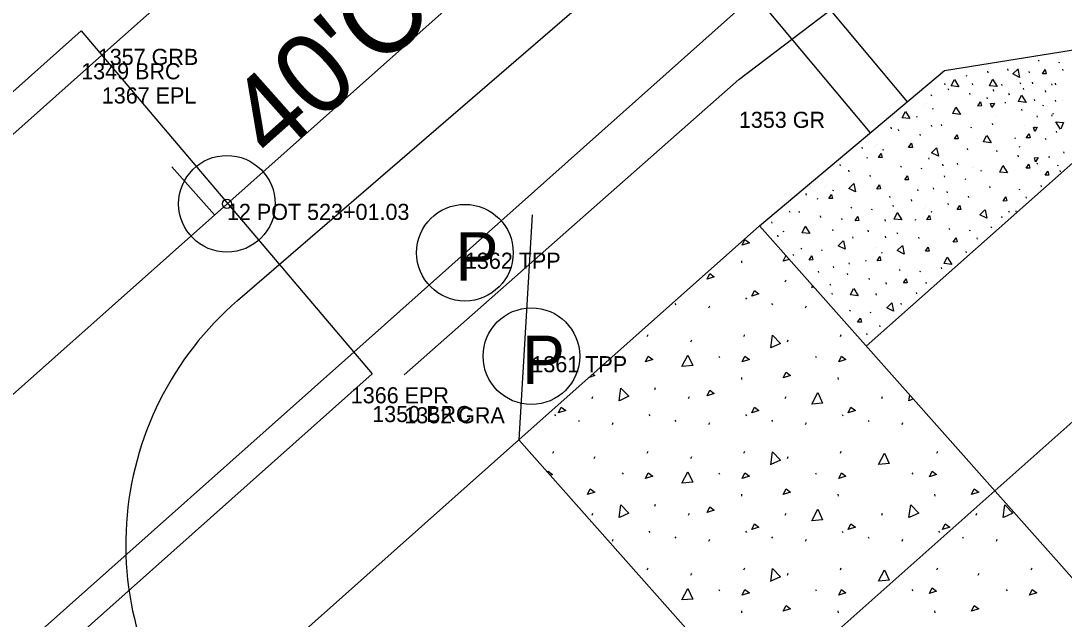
# Model space of a CAD drawing. Extents: x 50001 to 56005, y 49075 to 53926.
# Drawn here: x 53878.2 to 53943.1, y 51854.2 to 51891.3 of the extents above; entities that cross this region are included whole.
import ezdxf

# ---------------------------------------------------------------- set-up
doc = ezdxf.new("R2010")
doc.units = 0
for name, color, linetype in [('Level 1', 7, 'Continuous'), ('Level 15', 7, 'Continuous'), ('Level 18', 7, 'Continuous'), ('Level 19', 7, 'Continuous'), ('Level 20', 7, 'Continuous'), ('Level 3', 7, 'Continuous'), ('Level 5', 7, 'Continuous'), ('Level 51', 7, 'Continuous'), ('Level 53', 7, 'Continuous'), ('Level 55', 7, 'Continuous'), ('Level 57', 7, 'Continuous'), ('Level 59', 7, 'Continuous'), ('Level 7', 7, 'Continuous'), ('Level 8', 7, 'Continuous'), ('Level 9', 7, 'Continuous')]:
    doc.layers.add(name, color=color, linetype=linetype)

# ---------------------------------------------------------------- blocks, each defined once
blk = doc.blocks.new('PC')
at = {"layer": 'Level 1'}
for radius in [3, 0.282]:
    blk.add_circle((0, 0), radius, dxfattribs=at)
blk = doc.blocks.new('TPP')
at = {"layer": 'Level 9'}
blk.add_circle((0, 0), 3, dxfattribs=at)
blk.add_text('P', height=3, dxfattribs=at).set_placement((-0.589, -1.729))

msp = doc.modelspace()

# ---------------------------------------------------------------- linework, layer by layer
at = {"layer": 'Level 1'}
for p, q in [((52544.807, 50683.302), (55534.583, 53340.862)), ((52714.147, 50773.616), (54181.768, 52078.16)), ((53890.278, 51879.268), (53887.621, 51882.257))]:
    msp.add_line(p, q, dxfattribs=at)
at = {"layer": 'Level 15'}
for p, q in [((53910.003, 51879.272), (53909.18, 51865.296)), ((53909.18, 51865.296), (53924.129, 51878.584)), ((53924.129, 51878.584), (53953.361, 51845.698)), ((53923.006, 51876.413), (53923.02, 51876.288)), ((53925.731, 51875.108), (53925.786, 51875.233)), ((53923.263, 51874.123), (53923.318, 51874.04)), ((53918.882, 51873.77), (53918.937, 51873.687)), ((53920.993, 51873.499), (53921.049, 51873.623)), ((53924.882, 51873.77), (53924.937, 51873.687)), ((53926.993, 51873.499), (53927.049, 51873.623)), ((53917.158, 51871.709), (53917.213, 51871.834)), ((53919.869, 51871.39), (53919.925, 51871.514)), ((53923.158, 51871.709), (53923.213, 51871.834)), ((53925.869, 51871.39), (53925.925, 51871.514)), ((53929.158, 51871.709), (53929.213, 51871.834)), ((53915.604, 51870.502), (53915.659, 51870.418)), ((53921.604, 51870.502), (53921.659, 51870.418)), ((53927.604, 51870.502), (53927.659, 51870.418)), ((53923.006, 51869.171), (53923.02, 51869.046)), ((53929.006, 51869.171), (53929.02, 51869.046)), ((53917.622, 51868.434), (53917.677, 51868.559)), ((53913.731, 51867.865), (53913.786, 51867.99)), ((53919.731, 51867.865), (53919.786, 51867.99)), ((53925.731, 51867.865), (53925.786, 51867.99)), ((53931.731, 51867.865), (53931.786, 51867.99)), ((53911.406, 51866.881), (53911.461, 51866.797)), ((53917.263, 51866.881), (53917.318, 51866.797)), ((53923.263, 51866.881), (53923.318, 51866.797)), ((53929.263, 51866.881), (53929.318, 51866.797)), ((53912.882, 51866.527), (53912.937, 51866.444)), ((53914.993, 51866.256), (53915.049, 51866.381)), ((53918.882, 51866.527), (53918.937, 51866.444)), ((53920.993, 51866.256), (53921.049, 51866.381)), ((53924.882, 51866.527), (53924.937, 51866.444)), ((53926.993, 51866.256), (53927.049, 51866.381)), ((53930.882, 51866.527), (53930.937, 51866.444)), ((53932.993, 51866.256), (53933.049, 51866.381)), ((53460.734, 51466.679), (53909.18, 51865.296)), ((53938.412, 51832.41), (53909.18, 51865.296)), ((53911.301, 51864.466), (53911.356, 51864.591)), ((53913.869, 51864.147), (53913.925, 51864.272)), ((53917.158, 51864.466), (53917.213, 51864.591)), ((53919.869, 51864.147), (53919.925, 51864.272)), ((53923.158, 51864.466), (53923.213, 51864.591)), ((53925.869, 51864.147), (53925.925, 51864.272)), ((53929.158, 51864.466), (53929.213, 51864.591)), ((53935.158, 51864.466), (53935.213, 51864.591)), ((53915.604, 51863.259), (53915.659, 51863.176)), ((53921.604, 51863.259), (53921.659, 51863.176)), ((53927.604, 51863.259), (53927.659, 51863.176)), ((53933.604, 51863.259), (53933.659, 51863.176)), ((53923.006, 51861.928), (53923.02, 51861.803)), ((53929.006, 51861.928), (53929.02, 51861.803)), ((53935.006, 51861.928), (53935.02, 51861.803)), ((53917.622, 51861.192), (53917.677, 51861.317)), ((53913.731, 51860.623), (53913.786, 51860.748)), ((53919.731, 51860.623), (53919.786, 51860.748)), ((53925.731, 51860.623), (53925.786, 51860.748)), ((53931.731, 51860.623), (53931.786, 51860.748)), ((53937.588, 51860.623), (53937.643, 51860.748)), ((53914.993, 51859.013), (53915.049, 51859.138)), ((53917.263, 51859.638), (53917.318, 51859.555)), ((53918.882, 51859.285), (53918.937, 51859.202)), ((53920.993, 51859.013), (53921.049, 51859.138)), ((53923.263, 51859.638), (53923.318, 51859.555)), ((53924.882, 51859.285), (53924.937, 51859.202)), ((53926.993, 51859.013), (53927.049, 51859.138)), ((53929.263, 51859.638), (53929.318, 51859.555)), ((53930.882, 51859.285), (53930.937, 51859.202)), ((53932.993, 51859.013), (53933.049, 51859.138)), ((53935.263, 51859.638), (53935.318, 51859.555)), ((53936.739, 51859.285), (53936.795, 51859.202)), ((53938.85, 51859.013), (53938.906, 51859.138)), ((53917.158, 51857.223), (53917.213, 51857.348)), ((53923.158, 51857.223), (53923.213, 51857.348)), ((53929.158, 51857.223), (53929.213, 51857.348)), ((53935.158, 51857.223), (53935.213, 51857.348)), ((53941.015, 51857.223), (53941.07, 51857.348)), ((53919.869, 51856.904), (53919.925, 51857.029)), ((53925.869, 51856.904), (53925.925, 51857.029)), ((53937.726, 51856.904), (53937.782, 51857.029)), ((53921.604, 51856.016), (53921.659, 51855.933)), ((53927.604, 51856.016), (53927.659, 51855.933)), ((53933.604, 51856.016), (53933.659, 51855.933)), ((53939.461, 51856.016), (53939.516, 51855.933)), ((53923.006, 51854.685), (53923.02, 51854.56)), ((53929.006, 51854.685), (53929.02, 51854.56)), ((53935.006, 51854.685), (53935.02, 51854.56))]:
    msp.add_line(p, q, dxfattribs=at)
for points in [[(53923.061, 51877.384), (53923.227, 51877.73), (53923.505, 51877.522), (53923.061, 51877.384)], [(53925.614, 51876.392), (53925.776, 51876.73)], [(53925.976, 51876.505), (53925.614, 51876.392)], [(53920.874, 51875.278), (53921.04, 51875.625), (53921.318, 51875.417), (53920.874, 51875.278)], [(53923.649, 51874.22), (53923.816, 51874.567), (53924.093, 51874.359), (53923.649, 51874.22)], [(53927.379, 51874.766), (53927.432, 51874.867)], [(53927.513, 51874.776), (53927.393, 51874.766)], [(53924.829, 51871.002), (53924.939, 51871.795), (53925.436, 51871.282), (53924.842, 51871.007)], [(53917.061, 51870.141), (53917.227, 51870.488), (53917.505, 51870.28), (53917.061, 51870.141)], [(53919.318, 51869.851), (53919.692, 51870.559), (53919.984, 51869.907), (53919.331, 51869.851)], [(53923.061, 51870.141), (53923.227, 51870.488), (53923.505, 51870.28), (53923.061, 51870.141)], [(53929.061, 51870.141), (53929.227, 51870.488), (53929.505, 51870.28), (53929.061, 51870.141)], [(53925.614, 51869.149), (53925.781, 51869.496), (53926.058, 51869.288), (53925.614, 51869.149)], [(53913.776, 51869.381), (53913.9, 51869.288), (53913.547, 51869.178)], [(53915.419, 51867.722), (53915.529, 51868.515), (53916.026, 51868.002), (53915.432, 51867.727)], [(53920.874, 51868.035), (53921.04, 51868.382), (53921.318, 51868.174), (53920.874, 51868.035)], [(53927.379, 51867.523), (53927.754, 51868.231), (53928.045, 51867.579), (53927.393, 51867.523)], [(53933.419, 51867.722), (53933.468, 51868.077)], [(53933.678, 51867.841), (53933.432, 51867.727)], [(53911.649, 51866.977), (53911.816, 51867.324), (53912.093, 51867.116), (53911.649, 51866.977)], [(53923.649, 51866.977), (53923.816, 51867.324), (53924.093, 51867.116), (53923.649, 51866.977)], [(53929.649, 51866.977), (53929.816, 51867.324), (53930.093, 51867.116), (53929.649, 51866.977)], [(53924.829, 51863.759), (53924.939, 51864.552), (53925.436, 51864.039), (53924.842, 51863.764)], [(53931.529, 51863.772), (53931.904, 51864.48), (53932.195, 51863.828), (53931.543, 51863.772)], [(53910.968, 51863.285), (53911, 51863.351), (53911.277, 51863.143), (53911.134, 51863.098)], [(53917.061, 51862.898), (53917.227, 51863.245), (53917.505, 51863.037), (53917.061, 51862.898)], [(53919.318, 51862.609), (53919.692, 51863.316), (53919.984, 51862.664), (53919.331, 51862.609)], [(53923.061, 51862.898), (53923.227, 51863.245), (53923.505, 51863.037), (53923.061, 51862.898)], [(53929.061, 51862.898), (53929.227, 51863.245), (53929.505, 51863.037), (53929.061, 51862.898)], [(53934.691, 51863.004), (53934.857, 51863.351), (53935.135, 51863.143), (53934.691, 51863.004)], [(53913.456, 51861.906), (53913.622, 51862.253), (53913.9, 51862.045), (53913.456, 51861.906)], [(53925.614, 51861.907), (53925.781, 51862.253), (53926.058, 51862.045), (53925.614, 51861.907)], [(53937.313, 51861.906), (53937.479, 51862.253), (53937.757, 51862.045), (53937.313, 51861.906)], [(53915.419, 51860.479), (53915.529, 51861.272), (53916.026, 51860.759), (53915.432, 51860.484)], [(53920.874, 51860.793), (53921.04, 51861.14), (53921.318, 51860.932), (53920.874, 51860.793)], [(53927.379, 51860.281), (53927.754, 51860.988), (53928.045, 51860.336), (53927.393, 51860.281)], [(53933.419, 51860.479), (53933.529, 51861.272), (53934.026, 51860.759), (53933.432, 51860.484)], [(53939.276, 51860.479), (53939.386, 51861.272), (53939.883, 51860.759), (53939.289, 51860.484)], [(53923.649, 51859.735), (53923.816, 51860.082), (53924.093, 51859.873), (53923.649, 51859.735)], [(53929.649, 51859.735), (53929.816, 51860.082), (53930.093, 51859.873), (53929.649, 51859.735)], [(53935.506, 51859.735), (53935.673, 51860.082), (53935.95, 51859.873), (53935.506, 51859.735)], [(53924.829, 51856.517), (53924.939, 51857.31), (53925.436, 51856.797), (53924.842, 51856.521)], [(53931.529, 51856.53), (53931.904, 51857.237), (53932.195, 51856.585), (53931.543, 51856.53)], [(53919.318, 51855.366), (53919.692, 51856.073), (53919.984, 51855.421), (53919.331, 51855.366)], [(53923.061, 51855.656), (53923.227, 51856.003), (53923.505, 51855.794), (53923.061, 51855.656)], [(53929.061, 51855.656), (53929.227, 51856.003), (53929.505, 51855.794), (53929.061, 51855.656)], [(53934.691, 51855.762), (53934.857, 51856.108), (53935.135, 51855.9), (53934.691, 51855.762)], [(53940.918, 51855.656), (53941.084, 51856.003), (53941.362, 51855.794), (53940.918, 51855.656)], [(53925.614, 51854.664), (53925.781, 51855.011), (53926.058, 51854.803), (53925.614, 51854.664)], [(53937.313, 51854.664), (53937.479, 51855.011), (53937.757, 51854.803), (53937.313, 51854.664)]]:
    msp.add_lwpolyline(points, dxfattribs=at)
at = {"layer": 'Level 18'}
msp.add_line((53891.699, 51873.945), (53926.024, 51903.545), dxfattribs=at)
msp.add_arc((53904.761, 51858.799), 20, 130.77344, 221.63389, dxfattribs=at)
at = {"layer": 'Level 19'}
msp.add_line((52714.147, 50773.616), (54181.768, 52078.16), dxfattribs=at)
at = {"layer": 'Level 20'}
msp.add_line((53930.772, 51871.11), (54173.796, 52087.129), dxfattribs=at)
at = {"layer": 'Level 3'}
for p, q in [((53883.273, 51889.178), (54069.537, 52054.718)), ((53898.742, 51870.567), (54083.389, 52035.124)), ((53434.092, 51489.844), (53883.273, 51889.178)), ((53449.718, 51471.806), (53898.742, 51870.567))]:
    msp.add_line(p, q, dxfattribs=at)
at = {"layer": 'Level 5'}
for p, q in [((53432.563, 51491.203), (53881.993, 51890.68)), ((53881.993, 51890.68), (53900.074, 51869.402)), ((53900.074, 51869.402), (53451.19, 51470.163))]:
    msp.add_line(p, q, dxfattribs=at)
at = {"layer": 'Level 7'}
for p, q in [((53922.854, 51887.665), (53958.852, 51915.059)), ((53902.065, 51869.327), (53922.854, 51887.665))]:
    msp.add_line(p, q, dxfattribs=at)
at = {"layer": 'Level 8'}
for p, q in [((53933.325, 51886.292), (53921.868, 51899.962)), ((53931.026, 51884.365), (53919.596, 51898.002)), ((53935.625, 51888.219), (53953.195, 51891.04)), ((53941.504, 51888.801), (53941.444, 51888.86)), ((53924.129, 51878.584), (53935.625, 51888.219)), ((53939.549, 51888.32), (53939.573, 51888.232)), ((53942.79, 51888.71), (53942.726, 51888.729)), ((53942.951, 51888.305), (53942.976, 51888.217)), ((53937.045, 51887.867), (53936.981, 51887.886)), ((53938.29, 51888.175), (53938.314, 51888.087)), ((53940.867, 51888.166), (53940.892, 51888.078)), ((53935.631, 51887.423), (53935.655, 51887.336)), ((53935.843, 51887.113), (53935.867, 51887.025)), ((53937.348, 51887.426), (53937.372, 51887.338)), ((53938.643, 51887.037), (53938.667, 51886.949)), ((53939.216, 51887.291), (53939.189, 51887.378)), ((53940.317, 51887.485), (53940.341, 51887.397)), ((53940.557, 51887.039), (53940.53, 51887.126)), ((53941.074, 51887.495), (53941.098, 51887.407)), ((53941.883, 51886.976), (53941.907, 51886.888)), ((53942.271, 51887.397), (53942.296, 51887.309)), ((53942.501, 51887.431), (53942.525, 51887.343)), ((53934.789, 51886.743), (53934.813, 51886.655)), ((53937.175, 51886.819), (53937.199, 51886.731)), ((53938.254, 51886.551), (53938.278, 51886.463)), ((53939.379, 51886.247), (53939.443, 51886.23)), ((53939.614, 51886.81), (53939.638, 51886.723)), ((53941.2, 51886.422), (53941.224, 51886.334)), ((53942.498, 51886.393), (53942.522, 51886.305)), ((53942.977, 51886.338), (53942.977, 51886.338)), ((53934.374, 51886.047), (53934.374, 51886.047)), ((53934.503, 51886.153), (53934.503, 51886.153)), ((53934.939, 51885.83), (53934.875, 51885.849)), ((53940.456, 51885.749), (53940.429, 51885.836)), ((53941.716, 51886.066), (53941.781, 51886.048)), ((53933.956, 51885.326), (53933.892, 51885.346)), ((53938.596, 51884.945), (53938.62, 51884.858)), ((53938.859, 51885.404), (53938.859, 51885.404)), ((53941.362, 51885.417), (53941.386, 51885.329)), ((53942.268, 51885.482), (53942.293, 51885.394)), ((53942.43, 51885.512), (53942.366, 51885.531)), ((53932.296, 51884.701), (53932.321, 51884.614)), ((53932.754, 51884.572), (53932.778, 51884.484)), ((53934.79, 51884.834), (53934.814, 51884.746)), ((53935.412, 51884.878), (53935.437, 51884.79)), ((53937.327, 51884.668), (53937.263, 51884.688)), ((53940.603, 51884.837), (53940.603, 51884.837)), ((53941.228, 51884.758), (53941.252, 51884.67)), ((53942.56, 51884.464), (53942.584, 51884.376)), ((53934.086, 51884.278), (53934.11, 51884.19)), ((53940.056, 51884.011), (53939.992, 51884.03)), ((53941.936, 51883.921), (53941.909, 51884.008)), ((53930.483, 51883.47), (53930.508, 51883.382)), ((53931.285, 51883.506), (53931.285, 51883.506)), ((53931.413, 51883.612), (53931.413, 51883.612)), ((53931.85, 51883.289), (53931.786, 51883.309)), ((53937.038, 51883.389), (53937.062, 51883.301)), ((53938.854, 51883.257), (53938.878, 51883.169)), ((53940.324, 51883.475), (53940.26, 51883.494)), ((53943.013, 51883.181), (53943.037, 51883.093)), ((53929.124, 51882.401), (53929.148, 51882.313)), ((53930.867, 51882.786), (53930.803, 51882.805)), ((53934.632, 51882.801), (53934.656, 51882.713)), ((53935.507, 51882.405), (53935.531, 51882.317)), ((53936.412, 51882.472), (53936.436, 51882.384)), ((53940.186, 51882.963), (53940.21, 51882.875)), ((53941.426, 51882.405), (53941.365, 51882.463)), ((53942.098, 51882.877), (53942.163, 51882.86)), ((53929.664, 51882.031), (53929.689, 51881.943)), ((53930.996, 51881.737), (53931.02, 51881.649)), ((53932.952, 51882.219), (53932.891, 51882.277)), ((53934.237, 51882.127), (53934.174, 51882.147)), ((53937.385, 51882.191), (53937.385, 51882.191)), ((53937.513, 51882.296), (53937.513, 51882.296)), ((53937.95, 51881.974), (53937.886, 51881.993)), ((53941.578, 51882.034), (53941.578, 51882.034)), ((53942.711, 51882.313), (53942.648, 51882.333)), ((53942.786, 51882.015), (53942.811, 51881.927)), ((53928.324, 51881.071), (53928.324, 51881.071)), ((53935.602, 51881.694), (53935.627, 51881.606)), ((53936.967, 51881.47), (53936.903, 51881.49)), ((53941.607, 51881.089), (53941.631, 51881.001)), ((53927.019, 51880.586), (53927.044, 51880.498)), ((53928.195, 51880.965), (53928.195, 51880.965)), ((53928.76, 51880.749), (53928.696, 51880.768)), ((53932.204, 51880.436), (53932.228, 51880.348)), ((53933.948, 51880.848), (53933.973, 51880.76)), ((53934.923, 51880.949), (53934.947, 51880.861)), ((53935.765, 51880.716), (53935.789, 51880.628)), ((53937.096, 51880.422), (53937.121, 51880.334)), ((53938.423, 51881.022), (53938.447, 51880.934)), ((53940.338, 51880.812), (53940.274, 51880.831)), ((53927.777, 51880.245), (53927.713, 51880.264)), ((53932.417, 51879.864), (53932.441, 51879.776)), ((53933.563, 51880.209), (53933.588, 51880.121)), ((53934.424, 51879.756), (53934.424, 51879.756)), ((53935.829, 51879.977), (53935.853, 51879.889)), ((53940.682, 51880.394), (53940.706, 51880.306)), ((53925.988, 51879.523), (53926.012, 51879.435)), ((53926.575, 51879.491), (53926.599, 51879.403)), ((53927.907, 51879.197), (53927.931, 51879.109)), ((53929.862, 51879.678), (53929.802, 51879.736)), ((53931.148, 51879.587), (53931.084, 51879.606)), ((53934.295, 51879.65), (53934.295, 51879.65)), ((53934.86, 51879.433), (53934.797, 51879.453)), ((53939.16, 51879.163), (53939.185, 51879.075)), ((53939.614, 51879.519), (53939.638, 51879.431)), ((53940.049, 51879.532), (53940.073, 51879.445)), ((53924.887, 51878.842), (53924.911, 51878.755)), ((53929.225, 51879.042), (53929.25, 51878.954)), ((53931.912, 51878.972), (53931.936, 51878.884)), ((53933.877, 51878.929), (53933.813, 51878.949)), ((53938.517, 51878.549), (53938.541, 51878.461)), ((53925.243, 51878), (53925.267, 51877.912)), ((53925.671, 51878.208), (53925.607, 51878.227)), ((53928.675, 51878.362), (53928.699, 51878.274)), ((53929.905, 51877.908), (53929.929, 51877.82)), ((53930.859, 51878.307), (53930.883, 51878.219)), ((53931.944, 51877.935), (53931.969, 51877.847)), ((53932.675, 51878.175), (53932.699, 51878.087)), ((53934.007, 51877.881), (53934.031, 51877.793)), ((53935.962, 51878.363), (53935.902, 51878.421)), ((53937.248, 51878.271), (53937.184, 51878.291)), ((53937.642, 51877.843), (53937.667, 51877.755)), ((53926.773, 51877.137), (53926.713, 51877.196)), ((53931.335, 51877.215), (53931.335, 51877.215)), ((53926.214, 51876.833), (53926.238, 51876.745)), ((53928.059, 51877.046), (53927.995, 51877.065)), ((53931.206, 51877.109), (53931.206, 51877.109)), ((53931.771, 51876.892), (53931.707, 51876.912)), ((53936.959, 51876.992), (53936.983, 51876.904)), ((53928.707, 51876.056), (53928.731, 51875.968)), ((53929.678, 51876.282), (53929.702, 51876.195)), ((53930.788, 51876.389), (53930.724, 51876.408)), ((53932.873, 51875.822), (53932.813, 51875.88)), ((53935.428, 51876.008), (53935.452, 51875.92)), ((53927.77, 51875.766), (53927.794, 51875.678)), ((53929.586, 51875.634), (53929.61, 51875.547)), ((53930.917, 51875.34), (53930.942, 51875.252)), ((53934.159, 51875.73), (53934.095, 51875.75)), ((53928.513, 51874.986), (53928.537, 51874.898)), ((53931.977, 51875.057), (53932.001, 51874.969)), ((53934.47, 51875.089), (53934.494, 51875.001)), ((53928.682, 51874.352), (53928.618, 51874.371)), ((53931.362, 51874.376), (53931.386, 51874.288)), ((53933.87, 51874.451), (53933.894, 51874.363)), ((53929.783, 51873.281), (53929.723, 51873.339)), ((53932.916, 51873.793), (53932.94, 51873.705)), ((53931.069, 51873.19), (53931.005, 51873.209)), ((53931.589, 51872.399), (53931.613, 51872.311)), ((53930.78, 51871.91), (53930.805, 51871.822))]:
    msp.add_line(p, q, dxfattribs=at)
for points in [[(53940.189, 51888.324), (53940.296, 51887.801), (53939.87, 51888.013), (53940.182, 51888.318)], [(53941.887, 51888.279), (53941.948, 51888.03), (53941.717, 51888.019), (53941.887, 51888.279)], [(53936.245, 51887.669), (53936.524, 51887.214), (53936.051, 51887.268), (53936.24, 51887.661)], [(53938.619, 51887.679), (53938.898, 51887.224), (53938.425, 51887.278), (53938.614, 51887.671)], [(53937.86, 51886.274), (53937.921, 51886.025), (53937.69, 51886.015), (53937.86, 51886.274)], [(53940.421, 51886.696), (53940.7, 51886.242), (53940.227, 51886.295), (53940.417, 51886.688)], [(53933.202, 51885.692), (53933.481, 51885.237), (53933.008, 51885.291), (53933.197, 51885.684)], [(53936.342, 51885.951), (53936.621, 51885.496), (53936.148, 51885.55), (53936.337, 51885.943)], [(53938.563, 51885.931), (53938.494, 51886.178), (53938.725, 51886.196), (53938.563, 51885.931)], [(53942.845, 51884.591), (53942.552, 51885.037), (53943.026, 51884.998), (53942.849, 51884.599)], [(53940.881, 51884.301), (53940.942, 51884.052), (53940.711, 51884.042), (53940.881, 51884.301)], [(53941.234, 51884.444), (53941.165, 51884.691), (53941.395, 51884.708), (53941.234, 51884.444)], [(53933.569, 51883.706), (53933.63, 51883.457), (53933.399, 51883.447), (53933.569, 51883.706)], [(53936.424, 51884.237), (53936.485, 51883.988), (53936.254, 51883.978), (53936.424, 51884.237)], [(53938.252, 51884.201), (53938.531, 51883.746), (53938.058, 51883.8), (53938.247, 51884.193)], [(53931.692, 51883.076), (53931.753, 51882.827), (53931.522, 51882.816), (53931.692, 51883.076)], [(53935.139, 51883.43), (53935.246, 51882.908), (53934.82, 51883.12), (53935.132, 51883.425)], [(53940.871, 51882.418), (53940.932, 51882.169), (53940.701, 51882.159), (53940.871, 51882.418)], [(53941.283, 51882.561), (53941.214, 51882.808), (53941.444, 51882.826), (53941.283, 51882.561)], [(53939.256, 51882.322), (53939.535, 51881.867), (53939.062, 51881.921), (53939.251, 51882.314)], [(53942.044, 51881.984), (53942.105, 51881.735), (53941.874, 51881.725), (53942.044, 51881.984)], [(53930.003, 51881.215), (53930.109, 51880.692), (53929.683, 51880.905), (53929.995, 51881.209)], [(53931.6, 51881.125), (53931.661, 51880.876), (53931.43, 51880.866), (53931.6, 51881.125)], [(53933.335, 51881.696), (53933.396, 51881.447), (53933.165, 51881.437), (53933.335, 51881.696)], [(53928.602, 51880.535), (53928.664, 51880.286), (53928.432, 51880.276), (53928.602, 51880.535)], [(53936.58, 51879.85), (53936.641, 51879.601), (53936.41, 51879.591), (53936.58, 51879.85)], [(53939.435, 51880.381), (53939.496, 51880.132), (53939.265, 51880.121), (53939.435, 51880.381)], [(53930.245, 51879.155), (53930.306, 51878.906), (53930.075, 51878.896), (53930.245, 51879.155)], [(53932.692, 51879.402), (53932.971, 51878.948), (53932.498, 51879.001), (53932.687, 51879.394)], [(53934.703, 51879.22), (53934.764, 51878.971), (53934.533, 51878.96), (53934.703, 51879.22)], [(53938.15, 51879.574), (53938.257, 51879.051), (53937.83, 51879.264), (53938.143, 51879.568)], [(53926.977, 51878.556), (53927.256, 51878.101), (53926.783, 51878.154), (53926.972, 51878.548)], [(53936.345, 51877.84), (53936.407, 51877.591), (53936.175, 51877.581), (53936.345, 51877.84)], [(53929.344, 51877.66), (53929.451, 51877.137), (53929.025, 51877.349), (53929.337, 51877.654)], [(53933.013, 51877.359), (53933.12, 51876.836), (53932.694, 51877.048), (53933.006, 51877.353)], [(53934.61, 51877.269), (53934.672, 51877.02), (53934.441, 51877.01), (53934.61, 51877.269)], [(53927.391, 51876.717), (53927.452, 51876.468), (53927.221, 51876.457), (53927.391, 51876.717)], [(53931.613, 51876.679), (53931.674, 51876.43), (53931.443, 51876.419), (53931.613, 51876.679)], [(53935.8, 51876.648), (53936.079, 51876.193), (53935.606, 51876.247), (53935.795, 51876.64)], [(53933.256, 51875.299), (53933.317, 51875.05), (53933.086, 51875.04), (53933.256, 51875.299)], [(53929.987, 51874.699), (53930.267, 51874.244), (53929.794, 51874.298), (53929.983, 51874.691)], [(53932.355, 51873.804), (53932.462, 51873.281), (53932.036, 51873.493), (53932.348, 51873.798)], [(53930.402, 51872.861), (53930.463, 51872.612), (53930.232, 51872.601), (53930.402, 51872.861)]]:
    msp.add_lwpolyline(points, dxfattribs=at)

# ---------------------------------------------------------------- block references
at = {"layer": 'Level 1'}
msp.add_blockref('PC', (53891.047, 51879.951), dxfattribs=at)
at = {"layer": 'Level 9'}
for p in [(53905.834, 51876.918), (53909.962, 51870.495)]:
    msp.add_blockref('TPP', p, dxfattribs=at)

# ---------------------------------------------------------------- texts
at = {"layer": 'Level 18'}
msp.add_text("40'C", height=5, rotation=41.63338, dxfattribs=at).set_placement((53893.921, 51882.463))
at = {"layer": 'Level 51'}
msp.add_text('12 POT 523+01.03', height=1, dxfattribs=at).set_placement((53891.047, 51878.951))
at = {"layer": 'Level 53'}
for s, p in [('1367 EPL', (53883.273, 51886.178)), ('1366 EPR', (53898.742, 51867.567))]:
    msp.add_text(s, height=1, dxfattribs=at).set_placement(p)
at = {"layer": 'Level 55'}
for s, p in [('1349 BRC', (53881.993, 51887.68)), ('1350 BRC', (53900.074, 51866.402))]:
    msp.add_text(s, height=1, dxfattribs=at).set_placement(p)
at = {"layer": 'Level 57'}
for s, p in [('1357 GRB', (53883.022, 51888.572)), ('1353 GR', (53922.854, 51884.665)), ('1352 GRA', (53902.065, 51866.327))]:
    msp.add_text(s, height=1, dxfattribs=at).set_placement(p)
at = {"layer": 'Level 59'}
for s, p in [('1362 TPP', (53905.834, 51875.918)), ('1361 TPP', (53909.962, 51869.495))]:
    msp.add_text(s, height=1, dxfattribs=at).set_placement(p)

doc.saveas('drawing.dxf')
